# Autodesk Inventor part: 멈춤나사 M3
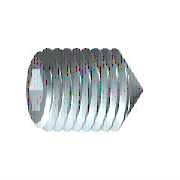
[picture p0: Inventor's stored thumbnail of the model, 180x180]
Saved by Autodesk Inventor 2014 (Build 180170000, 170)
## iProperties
IsCustomPart: 1
Created: 2012-02
Part Number: 멈춤나사 M3
Material: 강철, 연강
Description: 6각 소켓 머리 없는 멈춤 나사
Document SubType Name: Modeling
Standard: KS B 1028
Designer: mduedu
Standards Organization: KS
Language: ko-KR
Size Designation: 원추점 M3x6
Categories: <MemberInstance><Categories><Category DisplayName="조임쇠" InternalName="e4da775c-781d-43d5-af7c-5136215cf5a6" Mnemonic="FSTN"><Category DisplayName="볼트" InternalN
Density: 1 g/cm^3
Appearance: 노란색
Author: mduedu
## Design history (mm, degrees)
sketch "스케치1"
  geometry: L1 (0, 0)-(3.5, 0); L2 (6, 0.866)-(6, 1.5); L3 (6, 1.5)-(0, 1.5); L4 (6, 0.866)-(4, 0.866); L5 (4, 0.866)-(3.5, 0); L6 (0, -0.3)-(0, 1.8) reference; L7 (0, 1.5)-(0, 0)
  constraints: 13 end point, 3 parallel, 1 collinear, 1 perpendicular, 1 point on line
  dimensions: "d0" = 2 distance of L2.start L4.end (= INTI); "d1" = 60 deg angle of L5 L1; "d2" = 3 diameter of L3 L1 (= NND); "d3" = 1.73205 diameter of L4 L1 (= 1.1547 x SW); "d5" = 6 distance from line of L2 L3.end (= NLG)
revolve "본체" sketch "스케치1" stored, may be unused: angle "d6" = 90 deg
sketch "스케치2"
  geometry: L1 (-0.433, 0.75)-(0.433, 0.75); L2 (0.433, 0.75)-(0.866, 0); L3 (0.866, 0)-(0.433, -0.75); L4 (0.433, -0.75)-(-0.433, -0.75); L5 (-0.433, -0.75)-(-0.866, 0); L6 (-0.866, 0)-(-0.433, 0.75); 3 further points
  constraints: 12 end point, 1 coincident, 1 horizontal, 13 other
extrude "슬롯" join sketch "스케치2" taper "d7" = 0 deg; stored distance "d21" = 10
workaxis "Work Axis1"
workplane "Work Plane1"
body "Solid1"
feature "스레드" dims "d12" = 6 (= NLG), "d13" = 0
chamfer "모따기1" distance "d8" = 1.35 (computed from NND, SPD, FAWI); stored, may be unused: angle "d9" = 45 deg (= FAWI), second distance "d34" = 1.35 (computed from NND, SPD, FAWI)
chamfer "모따기2" distance "d10" = 0.30673 (= -0.5 x GD1 + 0.5 x NND); stored, may be unused: angle "d11" = 45 deg (= FAWI), second distance "d35" = 0.30673 (= -0.5 x GD1 + 0.5 x NND)
other parameters: "NND" = 3 [user parameter; used in 5 equation terms], "NLG" = 6 [user parameter; used in 2 equation terms], "INTI" = 2 [user parameter; used in 1 equation term], "FAWI" = 45 deg [user parameter; used in 4 equation terms], "SW" = 1.5 [user parameter; used in 2 equation terms], "GD1" = 2.38655 (= THREADDIA - 1.2269 x PTC) [user parameter; used in 2 equation terms], "d4" = 0, "FAWI1" = 45 deg [user parameter], "SPD" = 0.3 [user parameter; used in 2 equation terms], "d36" = 0, "d37" = 0, "GUL" = 0.30673 (= 0.61345 x PTC) [user parameter], "TOA" = 30 deg [user parameter], "THREADDIA" = 3 [user parameter; used in 1 equation term], "PTC" = 0.5 [user parameter; used in 4 equation terms], "GAL" = 0.30673 (= 0.61345 x PTC) [user parameter], "E0" = 1.7325 (= 1.155 x SW) [user parameter]
